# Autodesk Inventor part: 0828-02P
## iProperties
Shininess: 64.0
Length Units: 11269
Angle Units: 11279
Time Units: 11290
Mass Units: 11283
Length Display Precision: 3
Angle Display Precision: 2
Compacted: True
Part Number: 0828-02P
Document SubType Name: Modeling
Created: 2003-08
Designer: 40664
Manufacturer: Standard
Standards Organization: Custom
Density: 0.0
Volumn: 0.0
Area: 0.0
PropertySet Name: Model Information
Control State: 0
Master: False
Checked Out: False
Author: 40664
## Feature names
1. Revolution1
2. Extrusion1
3. Extrusion3
4. Extrusion4
5. Mirror1
6. Extrusion5
7. Chamfer1
8. Chamfer2
9. Fillet1
10. Fillet2
